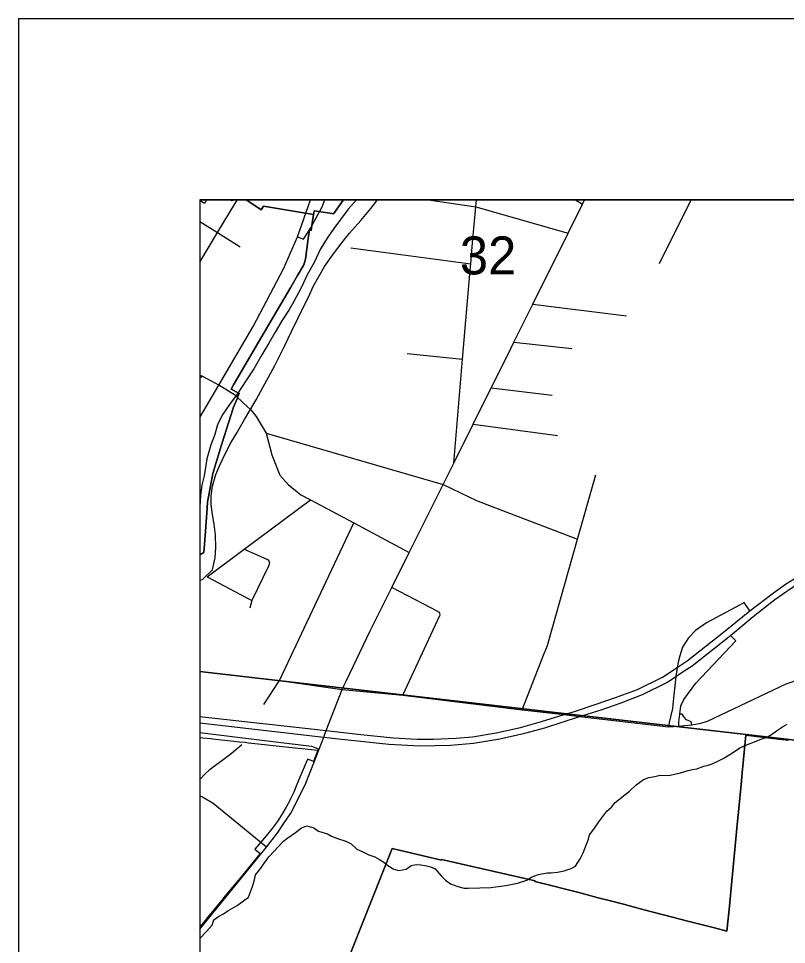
# Model space of a CAD drawing. Extents: x 0 to 34, y 0 to 22.
# Drawn here: x 2 to 2.424, y 20.49 to 21 of the extents above; entities that cross this region are included whole.
import ezdxf

# ---------------------------------------------------------------- set-up
doc = ezdxf.new("R2010")
doc.units = 0
for name, color, linetype in [('GM_X_City_Street', 7, 'Continuous'), ('GM_X_Corporation', 7, 'Continuous'), ('GM_X_County_Road', 7, 'Continuous'), ('GM_X_Interchange_Ramps', 7, 'Continuous'), ('GM_X_Interstate_Route', 7, 'Continuous'), ('GM_X_Minor_River', 7, 'Continuous'), ('GM_X_Section_Text', 7, 'Continuous'), ('GM_X_State_Route', 7, 'Continuous'), ('GM_X_State_Shield', 7, 'Continuous'), ('GM_X_Township_Road', 7, 'Continuous'), ('GM_X_US_Route', 7, 'Continuous'), ('SH_Cut_Line', 7, 'Continuous'), ('SH_Data', 7, 'Continuous')]:
    doc.layers.add(name, color=color, linetype=linetype)

msp = doc.modelspace()

# ---------------------------------------------------------------- linework, layer by layer
at = {"layer": 'GM_X_City_Street'}
for p, q in [((2.1197, 20.89845), (2.12068, 20.9)), ((2.30712, 20.9), (2.31097, 20.8977)), ((2.35356, 20.86492), (2.37091, 20.9)), ((2.1833, 20.87364), (2.24943, 20.86482)), ((2.28365, 20.8426), (2.33519, 20.83618)), ((2.27323, 20.8216), (2.30514, 20.81819)), ((2.21424, 20.8153), (2.24493, 20.81233)), ((2.1, 20.80206), (2.10124, 20.8028)), ((2.26068, 20.79637), (2.29424, 20.79247)), ((2.25072, 20.7764), (2.29723, 20.77022)), ((2.13651, 20.77143), (2.23415, 20.74317)), ((2.10395, 20.69238), (2.12864, 20.67919))]:
    msp.add_line(p, q, dxfattribs=at)
for points in [[(2.1, 20.89967), (2.1, 20.70435), (2.10213, 20.70573), (2.10303, 20.71736), (2.10404, 20.73039), (2.10428, 20.73344), (2.10707, 20.74917), (2.11201, 20.76504), (2.11234, 20.7661), (2.11577, 20.77714), (2.11847, 20.78584), (2.12088, 20.79138), (2.12101, 20.79167), (2.12175, 20.79337), (2.12005, 20.79426), (2.11832, 20.79516), (2.11736, 20.79567), (2.11858, 20.79804), (2.13862, 20.83225), (2.15012, 20.85188), (2.15393, 20.85839), (2.15735, 20.86423), (2.15819, 20.8674), (2.15967, 20.87869), (2.16006, 20.88112), (2.16042, 20.8834), (2.16142, 20.88325), (2.162, 20.8872), (2.16271, 20.89198), (2.1506, 20.89398), (2.13514, 20.89653), (2.1339, 20.89456), (2.12975, 20.89727), (2.12558, 20.9), (2.1194, 20.9), (2.11746, 20.89956), (2.11679, 20.9), (2.10375, 20.9), (2.10251, 20.89803)], [(2.17898, 20.9), (2.12558, 20.9), (2.12975, 20.89727), (2.1339, 20.89456), (2.13514, 20.89653), (2.1506, 20.89398), (2.16271, 20.89198), (2.16285, 20.8929), (2.16299, 20.89393), (2.17166, 20.89267), (2.17369, 20.89237), (2.17426, 20.89318), (2.17895, 20.89984)]]:
    msp.add_lwpolyline(points, close=True, dxfattribs=at)
for points in [[(3.02176, 20.9), (2.17898, 20.9), (2.17895, 20.89984), (2.17426, 20.89318), (2.17369, 20.89237), (2.17166, 20.89267), (2.16299, 20.89393), (2.16285, 20.8929), (2.16271, 20.89198), (2.162, 20.8872), (2.16142, 20.88325), (2.16042, 20.8834), (2.16006, 20.88112), (2.15967, 20.87869), (2.15819, 20.8674), (2.15735, 20.86423), (2.15393, 20.85839), (2.15012, 20.85188), (2.13862, 20.83225), (2.11858, 20.79804), (2.11736, 20.79567), (2.11832, 20.79516), (2.12005, 20.79426), (2.12175, 20.79337), (2.12101, 20.79167), (2.12088, 20.79138), (2.11847, 20.78584), (2.11577, 20.77714), (2.11234, 20.7661), (2.11201, 20.76504), (2.10707, 20.74917), (2.10428, 20.73344), (2.10404, 20.73039), (2.10303, 20.71736), (2.10213, 20.70573), (2.1, 20.70435), (2.1, 20.60383), (2.10169, 20.60364), (2.10629, 20.60314), (2.10702, 20.60306), (2.11712, 20.60196), (2.12192, 20.60144), (2.12494, 20.6011), (2.12684, 20.60089), (2.13562, 20.59993), (2.14216, 20.5992), (2.15431, 20.59787), (2.16165, 20.59707), (2.16515, 20.59668), (2.16267, 20.59053), (2.15947, 20.59182), (2.1592, 20.59117), (2.15589, 20.58347), (2.15352, 20.57788), (2.15175, 20.57367), (2.14979, 20.56954), (2.14975, 20.56945), (2.14756, 20.56531), (2.1452, 20.56127), (2.14264, 20.55734), (2.1399, 20.55355), (2.13568, 20.54838), (2.1304, 20.54215), (2.13332, 20.53974), (2.12204, 20.5261), (2.11403, 20.51642), (2.11213, 20.51412), (2.10609, 20.50682), (2.1041, 20.50442), (2.10388, 20.50414), (2.10376, 20.504), (2.1, 20.49946), (2.1, 20.38492)], [(2.1, 20.86575), (2.10978, 20.88199), (2.1197, 20.89845)], [(2.22609, 20.9), (2.25212, 20.89629), (2.30303, 20.8817)], [(2.24, 20.7549), (2.24493, 20.81233), (2.24912, 20.86127), (2.24943, 20.86482), (2.25042, 20.87646), (2.25212, 20.89629), (2.25253, 20.9)], [(2.1, 20.88819), (2.10978, 20.88199), (2.12224, 20.87408)], [(2.11959, 20.79225), (2.11046, 20.79786), (2.10124, 20.8028), (2.1, 20.80341)], [(2.11959, 20.79225), (2.12415, 20.78797), (2.12805, 20.78436), (2.13109, 20.78065), (2.13651, 20.77143), (2.13965, 20.75955), (2.14406, 20.74826), (2.14867, 20.7432), (2.15573, 20.73751), (2.16097, 20.73471), (2.18484, 20.72197), (2.21544, 20.70564)], [(2.27772, 20.61903), (2.28943, 20.64909), (2.29166, 20.65453), (2.29395, 20.66244), (2.30827, 20.713), (2.31834, 20.74854)], [(2.23415, 20.74317), (2.25255, 20.73436), (2.26063, 20.73129), (2.30827, 20.713)], [(2.10395, 20.69238), (2.12438, 20.70755), (2.16097, 20.73471)], [(2.13532, 20.62188), (2.14388, 20.63519), (2.18484, 20.72197)], [(2.12438, 20.70755), (2.137, 20.70194), (2.1376, 20.70159), (2.13805, 20.70114), (2.13829, 20.70058), (2.13837, 20.69999), (2.13831, 20.69934), (2.13785, 20.69812), (2.12864, 20.67919), (2.12759, 20.67504)], [(2.2119, 20.62705), (2.23235, 20.67092), (2.23246, 20.67138), (2.23237, 20.67206), (2.23208, 20.67257), (2.23167, 20.6729), (2.23127, 20.67323), (2.20585, 20.6864)], [(2.4246, 20.60225), (2.41931, 20.60287), (2.40563, 20.60447), (2.40105, 20.60501), (2.3991, 20.58432), (2.39848, 20.57778), (2.39724, 20.56465), (2.39657, 20.55756), (2.39196, 20.50886), (2.3906, 20.49701), (2.38373, 20.49879), (2.36911, 20.5026), (2.35568, 20.50607), (2.3549, 20.50628), (2.34427, 20.50904), (2.33364, 20.5118), (2.32566, 20.51387), (2.31962, 20.51544), (2.31769, 20.51598), (2.30971, 20.51805), (2.30173, 20.52013), (2.29377, 20.5222), (2.28475, 20.52443), (2.2849, 20.52481), (2.23323, 20.53652), (2.2332, 20.53611), (2.20601, 20.5425), (2.16768, 20.44589)], [(2.16768, 20.44589), (2.20601, 20.5425), (2.2332, 20.53611), (2.23323, 20.53652), (2.2849, 20.52481), (2.28475, 20.52443), (2.29377, 20.5222), (2.30173, 20.52013), (2.30971, 20.51805), (2.31769, 20.51598), (2.31962, 20.51544), (2.32566, 20.51387), (2.33364, 20.5118), (2.34427, 20.50904), (2.3549, 20.50628), (2.35568, 20.50607), (2.36911, 20.5026), (2.38373, 20.49879), (2.3906, 20.49701), (2.39196, 20.50886), (2.39657, 20.55756), (2.39724, 20.56465), (2.39848, 20.57778), (2.3991, 20.58432), (2.40105, 20.60501), (2.40563, 20.60447), (2.41931, 20.60287), (2.4246, 20.60225)]]:
    msp.add_lwpolyline(points, dxfattribs=at)
at = {"layer": 'GM_X_Corporation'}
msp.add_lwpolyline([(5.04518, 20.9), (2.1, 20.9), (2.1, 20.12706), (2.13415, 20.12341), (2.18047, 20.11893), (2.23003, 20.11359), (2.31914, 20.10381), (2.35745, 20.10011), (2.49398, 20.08589), (2.60767, 20.07635), (2.76246, 20.06345), (2.8394, 20.05622), (2.91774, 20.04882), (2.99895, 20.04051), (3.00624, 20.03956), (3.14042, 20.02292)], dxfattribs=at)
at = {"layer": 'GM_X_County_Road'}
for p, q in [((2.1, 20.64008), (2.14388, 20.63519)), ((2.14388, 20.63519), (2.17857, 20.63028))]:
    msp.add_line(p, q, dxfattribs=at)
for points in [[(2.37632, 20.6117), (2.37998, 20.61269), (2.42333, 20.63328), (2.43563, 20.63737)], [(2.17857, 20.63028), (2.2119, 20.62705), (2.27772, 20.61903), (2.3009, 20.61635), (2.30929, 20.61539), (2.35842, 20.60956), (2.36414, 20.61006), (2.36749, 20.61028), (2.37128, 20.61073), (2.3754, 20.61146), (2.37632, 20.6117)]]:
    msp.add_lwpolyline(points, dxfattribs=at)
at = {"layer": 'GM_X_Interchange_Ramps'}
for p, q in [((2.1, 20.60648), (2.12219, 20.60375)), ((2.12219, 20.60375), (2.16158, 20.59891)), ((2.16158, 20.59891), (2.16571, 20.59733))]:
    msp.add_line(p, q, dxfattribs=at)
for points in [[(2.162, 20.88609), (2.16741, 20.89615), (2.16899, 20.9)], [(2.15386, 20.87971), (2.15711, 20.87842), (2.16123, 20.88465), (2.162, 20.88609)], [(2.4032, 20.67352), (2.40016, 20.67812), (2.39757, 20.67661), (2.37938, 20.66689), (2.37331, 20.66277), (2.36944, 20.65875), (2.36613, 20.65349), (2.36475, 20.64877), (2.36376, 20.64531), (2.36318, 20.64235), (2.36246, 20.63737), (2.36085, 20.62187)], [(2.36414, 20.61006), (2.36418, 20.61216), (2.36468, 20.61666), (2.36517, 20.62117), (2.36686, 20.62474), (2.37356, 20.63367), (2.39551, 20.65705), (2.39269, 20.66005)], [(2.36085, 20.62187), (2.36061, 20.61965), (2.35875, 20.61198), (2.35842, 20.60956)], [(2.37128, 20.61073), (2.37097, 20.61233), (2.36829, 20.61341), (2.36704, 20.61492), (2.36597, 20.61653), (2.36468, 20.61666)]]:
    msp.add_lwpolyline(points, dxfattribs=at)
at = {"layer": 'GM_X_Interstate_Route'}
msp.add_lwpolyline([(2.1, 20.78008), (2.11046, 20.79786), (2.12938, 20.83027), (2.14611, 20.86203), (2.15386, 20.87971), (2.16098, 20.9)], dxfattribs=at)
at = {"layer": 'GM_X_Minor_River'}
for points in [[(2.15054, 20.82758), (2.15429, 20.83511), (2.15666, 20.84001), (2.16001, 20.84679), (2.16258, 20.85225), (2.16553, 20.8579), (2.16867, 20.86335), (2.17276, 20.86898), (2.17763, 20.87554), (2.18248, 20.88172), (2.18869, 20.88863), (2.19431, 20.89537), (2.19798, 20.9)], [(2.18638, 20.9), (2.18178, 20.89485), (2.1775, 20.88923), (2.17381, 20.88435), (2.17049, 20.87948), (2.16658, 20.87309), (2.16302, 20.86555), (2.1591, 20.85878)], [(2.1591, 20.85878), (2.15612, 20.852), (2.1518, 20.84409), (2.14905, 20.8392), (2.14515, 20.83338), (2.14162, 20.82718), (2.13809, 20.82116), (2.13417, 20.81458), (2.12986, 20.80687), (2.12576, 20.80087), (2.12049, 20.79298), (2.1164, 20.78736), (2.1123, 20.78135), (2.10974, 20.77608), (2.10811, 20.77022), (2.10612, 20.76513), (2.10388, 20.75737), (2.10304, 20.75264), (2.10238, 20.7479), (2.10114, 20.74279), (2.10028, 20.73729), (2.1, 20.73104)], [(2.1, 20.6902), (2.10169, 20.69108), (2.10691, 20.69611), (2.10836, 20.70274), (2.10885, 20.70843), (2.1086, 20.71547), (2.10795, 20.72137), (2.10691, 20.72672), (2.10625, 20.73205), (2.10616, 20.73699), (2.10702, 20.7423), (2.10884, 20.74873), (2.11103, 20.75382), (2.11438, 20.76079), (2.11714, 20.76606), (2.12027, 20.77132), (2.12459, 20.77903), (2.12753, 20.78392), (2.13106, 20.78993), (2.13498, 20.79708), (2.13793, 20.80235), (2.14127, 20.80875), (2.14443, 20.81496), (2.14679, 20.81986), (2.15054, 20.82758)], [(2.40995, 20.60309), (2.41245, 20.60374), (2.41517, 20.60534), (2.41792, 20.60751), (2.42123, 20.60965), (2.42395, 20.61106)], [(2.1, 20.49301), (2.10365, 20.49681), (2.10683, 20.50029), (2.10771, 20.50329), (2.11025, 20.50509), (2.11296, 20.5065), (2.1155, 20.50829), (2.12056, 20.51112), (2.12682, 20.51581), (2.12895, 20.52161), (2.13005, 20.52536), (2.13072, 20.528), (2.13312, 20.53094), (2.13614, 20.53537), (2.13795, 20.53796), (2.14092, 20.54107), (2.14311, 20.54345), (2.14608, 20.54655), (2.14843, 20.54836), (2.15273, 20.55141), (2.15606, 20.55393), (2.15896, 20.55514), (2.16291, 20.55403), (2.1655, 20.55221), (2.17038, 20.55068), (2.17261, 20.54945), (2.17598, 20.54817), (2.18048, 20.54665), (2.18346, 20.5452), (2.18657, 20.54222), (2.19031, 20.54054), (2.1931, 20.53909), (2.19648, 20.538), (2.19908, 20.53657), (2.20149, 20.53495), (2.2037, 20.53315), (2.20704, 20.53111), (2.20967, 20.53043), (2.21369, 20.53121), (2.21662, 20.53318), (2.2193, 20.53383), (2.22195, 20.53353), (2.22422, 20.53324), (2.22723, 20.53255), (2.22985, 20.5313), (2.23312, 20.52756), (2.23549, 20.52518), (2.23827, 20.52316), (2.2422, 20.52167), (2.24577, 20.52076), (2.24805, 20.52066), (2.25433, 20.52098), (2.26042, 20.5211), (2.26881, 20.52209), (2.27514, 20.52353), (2.28033, 20.52503), (2.28268, 20.52683), (2.28673, 20.52818), (2.29151, 20.52913), (2.2938, 20.52922), (2.29723, 20.52946), (2.30087, 20.53026), (2.30472, 20.53162), (2.30724, 20.53285), (2.30968, 20.53693), (2.31133, 20.54009), (2.31323, 20.54495), (2.31429, 20.54776), (2.31495, 20.55001), (2.31735, 20.55314), (2.31998, 20.55721), (2.32159, 20.55943), (2.32439, 20.56311), (2.32695, 20.56529), (2.32895, 20.56786), (2.33444, 20.5722), (2.33699, 20.57418), (2.34055, 20.57765), (2.34465, 20.58052), (2.34755, 20.58173), (2.35099, 20.58234), (2.35387, 20.58299), (2.35709, 20.58285), (2.35938, 20.58295), (2.36513, 20.58423), (2.36936, 20.58557), (2.37166, 20.58605), (2.37415, 20.58652), (2.378, 20.58788), (2.38031, 20.58854), (2.38261, 20.58921), (2.38532, 20.59043), (2.38862, 20.59219), (2.3931, 20.59485), (2.39778, 20.59808), (2.40146, 20.59964), (2.40493, 20.60102), (2.40995, 20.60309)]]:
    msp.add_lwpolyline(points, dxfattribs=at)
at = {"layer": 'GM_X_State_Route'}
for points in [[(2.17653, 20.60309), (2.2042, 20.59998), (2.22141, 20.5991), (2.23819, 20.59954), (2.25091, 20.60064), (2.26539, 20.60294), (2.27921, 20.60612), (2.29017, 20.60908), (2.30929, 20.61539), (2.32132, 20.61906), (2.33239, 20.6229), (2.34402, 20.6275), (2.35784, 20.6343), (2.36246, 20.63737), (2.36705, 20.64041), (2.37143, 20.6433), (2.39269, 20.66005), (2.40521, 20.67049), (2.41716, 20.67981), (2.42561, 20.68563), (2.43897, 20.69448), (2.44982, 20.70062)], [(2.4032, 20.67352), (2.4163, 20.68356), (2.42302, 20.68819), (2.43008, 20.69259)], [(2.1, 20.61531), (2.16967, 20.60755), (2.18874, 20.6054), (2.20678, 20.60353), (2.21983, 20.60276), (2.2286, 20.60282), (2.24138, 20.60342), (2.25037, 20.60419), (2.26342, 20.60627), (2.27674, 20.60923), (2.28842, 20.61258), (2.3009, 20.61635), (2.30662, 20.61808), (2.31809, 20.62201), (2.32916, 20.62579), (2.34135, 20.6302), (2.35517, 20.637), (2.36318, 20.64235), (2.36877, 20.64599), (2.38879, 20.66178), (2.4032, 20.67352)], [(2.1, 20.6119), (2.16828, 20.60401), (2.17653, 20.60309)]]:
    msp.add_lwpolyline(points, dxfattribs=at)
at = {"layer": 'GM_X_State_Shield'}
for points in [[(2.5115, 20.9), (2.1, 20.9), (2.1, 20.64018), (2.4809, 20.59626)], [(2.1, 20.64018), (2.1, 20.12611), (2.43388, 20.09141), (2.4809, 20.59626)]]:
    msp.add_lwpolyline(points, close=True, dxfattribs=at)
at = {"layer": 'GM_X_Township_Road'}
for points in [[(2.1, 20.58049), (2.10061, 20.58117), (2.10263, 20.58344), (2.10578, 20.58622), (2.11726, 20.595), (2.12324, 20.59982)], [(2.13674, 20.54324), (2.10743, 20.56742), (2.10149, 20.57095), (2.1, 20.57156)]]:
    msp.add_lwpolyline(points, dxfattribs=at)
at = {"layer": 'GM_X_US_Route'}
msp.add_line((2.16828, 20.60401), (2.16954, 20.60723), dxfattribs=at)
for points in [[(2.18076, 20.63487), (2.19398, 20.66258), (2.20585, 20.6864), (2.21544, 20.70564), (2.23415, 20.74317), (2.24, 20.7549), (2.25072, 20.7764), (2.26068, 20.79637), (2.26975, 20.81457), (2.27323, 20.8216), (2.28365, 20.8426), (2.30303, 20.8817), (2.31097, 20.8977), (2.31211, 20.9)], [(2.16954, 20.60723), (2.16967, 20.60755), (2.17857, 20.63028), (2.17964, 20.63252), (2.18076, 20.63487)], [(2.14585, 20.55567), (2.15013, 20.56199), (2.15813, 20.5776), (2.16315, 20.59067), (2.16571, 20.59733), (2.16828, 20.60401)], [(2.1, 20.49816), (2.13674, 20.54324), (2.14299, 20.55146), (2.14585, 20.55567)]]:
    msp.add_lwpolyline(points, dxfattribs=at)
at = {"layer": 'SH_Cut_Line'}
msp.add_lwpolyline([(5.67696, 20.9), (2.1, 20.9), (2.1, 17.35231)], dxfattribs=at)
at = {"layer": 'SH_Data'}
for p, q in [((2, 21), (9, 21)), ((2, 21), (2, 14)), ((2.1, 20.9), (2.1, 14.1)), ((2.1, 20.9), (8.9, 20.9))]:
    msp.add_line(p, q, dxfattribs=at)

# ---------------------------------------------------------------- texts
at = {"layer": 'GM_X_Section_Text'}
msp.add_text('32', height=0.020928, rotation=0, dxfattribs=at).set_placement((2.24338, 20.85898))

doc.saveas('drawing.dxf')
